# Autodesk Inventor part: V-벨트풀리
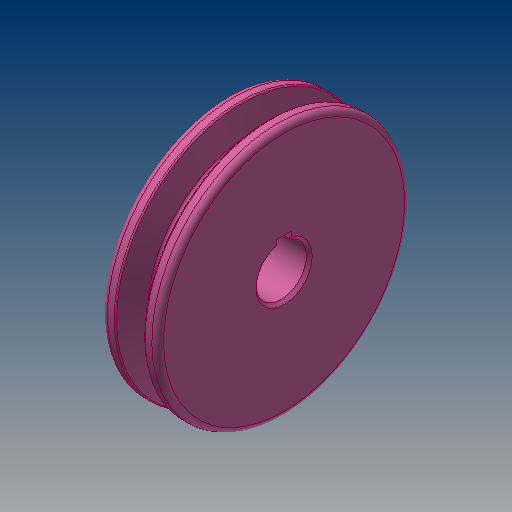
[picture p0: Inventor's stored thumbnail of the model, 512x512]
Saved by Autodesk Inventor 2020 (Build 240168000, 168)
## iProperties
Created: 2018-11
Part Number: V-벨트풀리
Material: 알루미늄 6061
Document SubType Name: Modeling
Designer: mduedu
Density: 1 g/cm^3
Appearance: 분홍색
Author: mduedu
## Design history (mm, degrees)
sketch "스케치1"
  geometry: L1 (-9.5, 0)-(9.5, 0); L2 (9.5, 0)-(9.5, 42.7); L3 (9.5, 42.7)-(-9.5, 42.7); L4 (-9.5, 42.7)-(-9.5, 0); L5 (-4.877, 42.7)-(-1.953, 33.7); L6 (-1.953, 33.7)-(1.953, 33.7); L7 (1.953, 33.7)-(4.877, 42.7); L8 (0, 0)-(0, 42.7); L9 (-9.5, 40)-(9.5, 40); 3 further points
  constraints: 18 end point, 8 point on line, 3 perpendicular, 2 midpoint, 2 parallel, 1 coincident, 1 horizontal, 1 other
  dimensions: "d0" = 85.4 diameter of L3 L1; "d2" = 19 distance of L2.end L3.end; "d3" = 80 diameter of L9 L1; "d4" = 36 deg angle of L7 L5; "d5" = 6.3 distance between parallel lines of L6 L9; "d6" = 8 distance of point (4, 40) point (-4, 40)
revolve "회전1" sketch "스케치1" stored, may be unused: angle "d7" = 90 deg
sketch "스케치2"
  geometry: L1 (-2.5, 8.124)-(2.5, 8.124); L2 (2.5, 8.124)-(2.5, 10.8); L3 (2.5, 10.8)-(-2.5, 10.8); L4 (-2.5, 10.8)-(-2.5, 8.124); A1 r 8.5 centre (0, 0) between (-2.5, 8.124) and (2.5, 8.124); 1 further point
  constraints: 8 end point, 2 parallel, 2 point on circle, 1 centre point, 1 coincident, 1 horizontal, 1 perpendicular
  dimensions: "d8" = 17 diameter of A1; "d10" = 19.3 dimension on A1 L3; "d11" = 5 distance of L2.end L3.end
extrude "돌출1" cut sketch "스케치2" extent not by distance; stored distance "d12" = 10; taper "d13" = 0 deg
chamfer "모따기1" distance "d14" = 1; stored, may be unused: second distance "d15" = 2, angle "d16" = 45 deg
fillet "모깎기1" dims "d17" = 1, "d18" = 0.5, "d19" = 2
sketch "스케치3"
  geometry: C1 r 17.5 at (0, 0); C2 r 28.5 at (0, 0); 1 further point
  constraints: 2 centre point, 2 coincident
  dimensions: "d20" = 35 diameter of C1; "d23" = 57 diameter of C2
extrude "돌출2" cut sketch "스케치3" distance "d24" = 9.5; taper "d25" = 0 deg
fillet "모깎기2" dims "d26" = 3
node "솔리드1"
